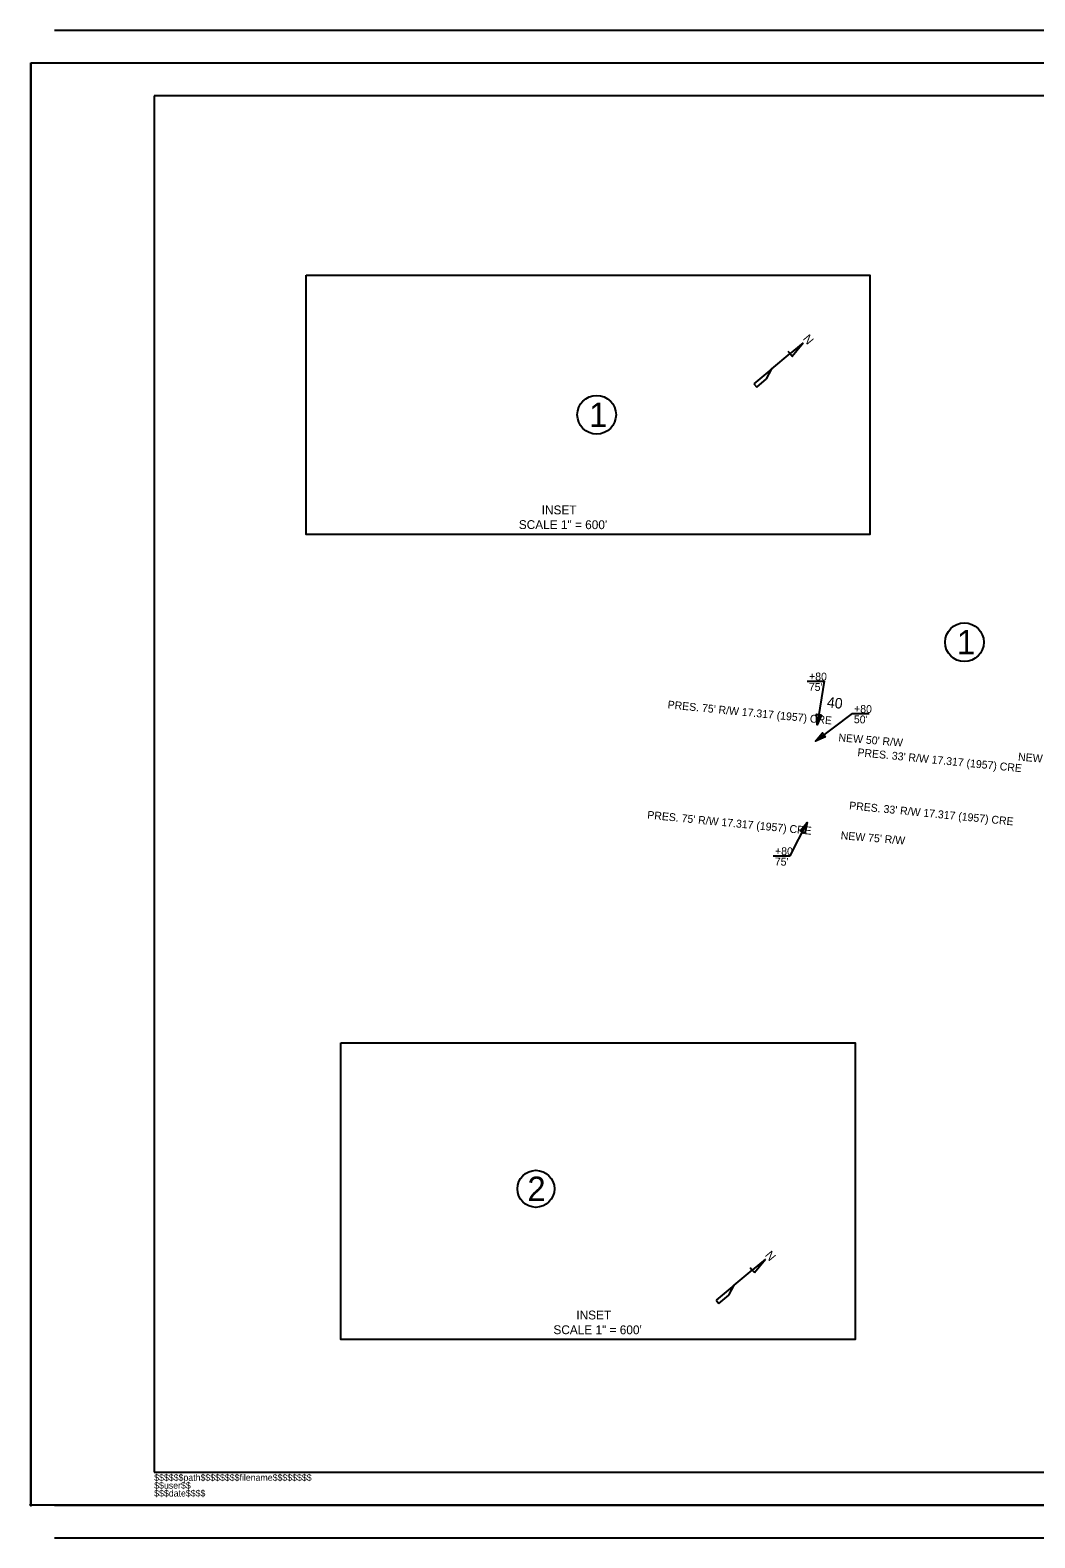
# Model space of a CAD drawing. Extents: x -9777 to -4387, y 40993 to 44443.
# Drawn here: x -9777 to -7477, y 40993 to 44443 of the extents above; entities that cross this region are included whole.
import ezdxf

# ---------------------------------------------------------------- set-up
doc = ezdxf.new("R2010")
doc.units = 0
for name, color, linetype in [('RD_EX_DV_TX_Prop', 7, 'Continuous'), ('RD_EX_Misc', 7, 'Continuous'), ('RD_EX_RW_TX', 7, 'Continuous'), ('RD_HC_TX_Sta50', 7, 'Continuous'), ('RD_PD_RW_TX', 7, 'Continuous'), ('RD_SHT_Bndy', 7, 'Continuous'), ('RD_SHT_ID', 7, 'Continuous'), ('RD_SHT_IplotShp', 7, 'Continuous'), ('RD_SHT_Snap', 7, 'Continuous'), ('RD_TX_Drainage', 7, 'Continuous')]:
    doc.layers.add(name, color=color, linetype=linetype)

msp = doc.modelspace()

# ---------------------------------------------------------------- linework, layer by layer
at = {"layer": 'RD_EX_DV_TX_Prop'}
for centre, radius in [((-8480.1, 43562.9), 44.3), ((-7638.6, 43042.4), 44.3), ((-8619.2, 41791.6), 42.4)]:
    msp.add_circle(centre, radius, dxfattribs=at)
at = {"layer": 'RD_EX_Misc'}
for p, q in [((-8007.3, 43727.8), (-8037.4, 43702.7)), ((-8032.4, 43696.6), (-8007.3, 43727.8)), ((-8007.3, 43727.8), (-8007.3, 43727.8)), ((-8079.1, 43667.8), (-8037.4, 43702.7)), ((-8042.4, 43708.7), (-8037.4, 43702.7)), ((-8037.4, 43702.7), (-8032.4, 43696.6)), ((-8032.4, 43696.6), (-8032, 43696.9)), ((-8079.1, 43667.8), (-8120.1, 43633.5)), ((-8113.8, 43626), (-8091.1, 43645)), ((-8091.3, 43644.9), (-8079.1, 43667.8)), ((-8091.1, 43645), (-8091.3, 43644.9)), ((-8120.1, 43633.5), (-8113.8, 43626)), ((-8129, 41611.8), (-8124, 41605.8)), ((-8093.9, 41630.9), (-8124, 41605.8)), ((-8119, 41599.8), (-8093.9, 41630.9)), ((-8093.9, 41630.9), (-8093.9, 41630.9)), ((-8165.7, 41570.9), (-8124, 41605.8)), ((-8124, 41605.8), (-8119, 41599.8)), ((-8119, 41599.8), (-8118.6, 41600.1)), ((-8165.7, 41570.9), (-8206.7, 41536.6)), ((-8200.4, 41529.1), (-8177.7, 41548.1)), ((-8177.9, 41548), (-8165.7, 41570.9)), ((-8177.7, 41548.1), (-8177.9, 41548)), ((-8206.7, 41536.6), (-8200.4, 41529.1))]:
    msp.add_line(p, q, dxfattribs=at)
at = {"layer": 'RD_PD_RW_TX'}
for p, q in [((-7998.6, 42953.3), (-7959.6, 42953.3)), ((-7959.6, 42953.3), (-7975.2, 42853.3)), ((-7895.6, 42879), (-7979.1, 42816)), ((-7895.6, 42879), (-7856.6, 42879)), ((-8037.4, 42553.4), (-7998.4, 42629.5)), ((-8076.4, 42553.4), (-8037.4, 42553.4))]:
    msp.add_line(p, q, dxfattribs=at)
for points in [[(-9144.6, 43882.2), (-7855.1, 43882.2), (-7855.1, 43289.2), (-9144.6, 43289.2)], [(-9065.4, 42126), (-7888.3, 42126), (-7888.3, 41446.9), (-9065.4, 41446.9)]]:
    msp.add_lwpolyline(points, close=True, dxfattribs=at)
at = {"layer": 'RD_SHT_Bndy'}
for p, q in [((-9720.7, 44443), (-4440.7, 44443)), ((-9720.7, 44368), (-4440.7, 44368)), ((-4467.7, 44293), (-9492.7, 44293)), ((-9492.7, 44293), (-9492.7, 41143)), ((-9492.7, 41143), (-4467.7, 41143)), ((-9720.7, 41068), (-4440.7, 41068)), ((-9720.7, 40993), (-4440.7, 40993))]:
    msp.add_line(p, q, dxfattribs=at)
at = {"layer": 'RD_SHT_IplotShp'}
msp.add_lwpolyline([(-9774.7, 44368), (-4386.7, 44368), (-4386.7, 41068), (-9774.7, 41068)], close=True, dxfattribs=at)
at = {"layer": 'RD_SHT_Snap'}
msp.add_line((-9774.7, 44368), (-9774.7, 41068), dxfattribs=at)
msp.add_circle((-9774.7, 41068), 1.82, dxfattribs=at)
at = {"layer": 'RD_TX_Drainage'}
for points in [[(-7965.6, 42876.1), (-7975.2, 42853.3), (-7977.4, 42877.9)], [(-7956.3, 42825.7), (-7979.1, 42816), (-7963.5, 42835.2)], [(-8014.7, 42610.9), (-7998.4, 42629.5), (-8004, 42605.4)]]:
    msp.add_lwpolyline(points, close=True, dxfattribs=at)

# ---------------------------------------------------------------- texts
at = {"layer": 'RD_EX_DV_TX_Prop'}
for s, p in [('1', (-8497.2, 43534.9)), ('1', (-7655.6, 43014.4)), ('2', (-8638.6, 41763.6))]:
    msp.add_text(s, height=56, dxfattribs=at).set_placement(p)
at = {"layer": 'RD_EX_Misc'}
for p in [(-8009.5, 43736.2), (-8096.1, 41639.3)]:
    msp.add_text('N', height=20, rotation=309.8881, dxfattribs=at).set_placement(p)
at = {"layer": 'RD_EX_RW_TX'}
for s, height, rotation, p in [('INSET', 20.25, 359.9137, (-8605.9, 43335.1)), ('SCALE 1" = 600\'', 20.25, 359.9137, (-8658.3, 43301.4)), ("PRES. 75' R/W 17.317 (1957) CRE", 18, 354.3832, (-8318.4, 42891.1)), ("PRES. 33' R/W 17.317 (1957) CRE", 18, 354.3832, (-7883.9, 42781.9)), ("PRES. 33' R/W 17.317 (1957) CRE", 18, 354.3832, (-7902.9, 42660.1)), ("PRES. 75' R/W 17.317 (1957) CRE", 18, 354.3832, (-8365, 42638.8)), ('INSET', 20.25, 359.9137, (-8526.7, 41492.8)), ('SCALE 1" = 600\'', 20.25, 359.9137, (-8579.1, 41459.1))]:
    msp.add_text(s, height=height, rotation=rotation, dxfattribs=at).set_placement(p)
at = {"layer": 'RD_HC_TX_Sta50'}
msp.add_text('40', height=24, rotation=354.095, dxfattribs=at).set_placement((-7954, 42893.6))
at = {"layer": 'RD_PD_RW_TX'}
for s, rotation, p in [('+80', 358.7687, (-7994.2, 42955.4)), ("75'", 358.7687, (-7994.7, 42931.4)), ('+80', 358.7687, (-7891.2, 42881.2)), ("50'", 358.7687, (-7891.7, 42857.2)), ("NEW 50' R/W", 355.2082, (-7927.3, 42815.7)), ("NEW 50' R/W", 355.2082, (-7516.3, 42771.7)), ("NEW 75' R/W", 355.2082, (-7922.2, 42591.7)), ('+80', 358.7687, (-8072.1, 42555.6)), ("75'", 358.7687, (-8072.6, 42531.6))]:
    msp.add_text(s, height=18, rotation=rotation, dxfattribs=at).set_placement(p)
at = {"layer": 'RD_SHT_ID'}
for s, p in [('$$$$$$path$$$$$$$$filename$$$$$$$$', (-9492.7, 41123.5)), ('$$user$$', (-9492.7, 41105.5)), ('$$$date$$$$', (-9492.7, 41087.5))]:
    msp.add_text(s, height=15, rotation=360, dxfattribs=at).set_placement(p)

doc.saveas('drawing.dxf')
